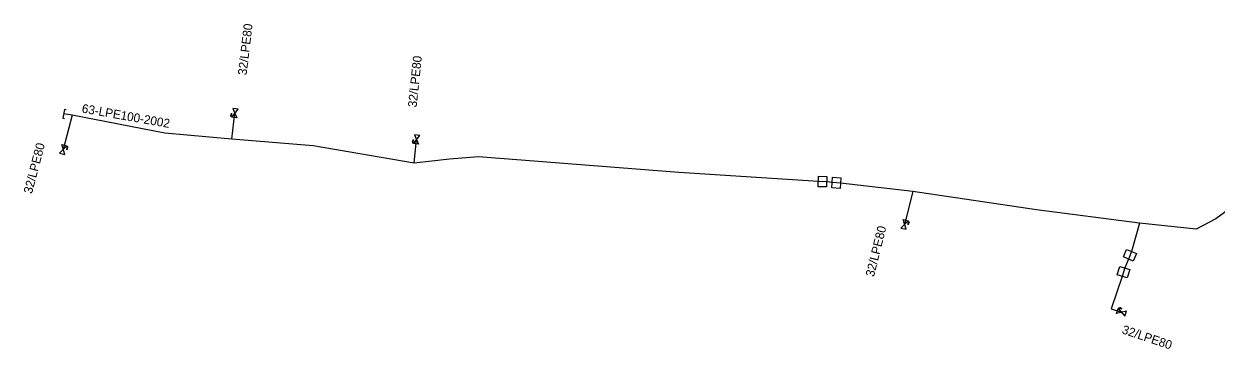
# Model space of a CAD drawing. Extents: x -787723 to -786204, y -1153846 to -1152384.
# Drawn here: x -787461.8 to -787326.5, y -1152544.5 to -1152507.6 of the extents above; entities that cross this region are included whole.
import ezdxf

# ---------------------------------------------------------------- set-up
doc = ezdxf.new("R2010")
doc.units = 0
for name, color, linetype in [('Vrstva 1', 7, 'Continuous'), ('Vrstva 21', 7, 'Continuous'), ('Vrstva 22', 7, 'Continuous'), ('Vrstva 29', 7, 'Continuous'), ('Vrstva 31', 7, 'Continuous'), ('Vrstva 32', 7, 'Continuous')]:
    doc.layers.add(name, color=color, linetype=linetype)

# ---------------------------------------------------------------- blocks, each defined once
blk = doc.blocks.new('DEC063-SN')
at = {"layer": 'Vrstva 1'}
for p, q in [((-0.5, -0.3), (0.5, 0.3)), ((0.5, -0.3), (-0.5, 0.3)), ((-0.5, 0.3), (-0.5, -0.3)), ((0.5, 0.3), (0.5, -0.3)), ((0.126, -0.318), (0.126, -0.458)), ((0.126, -0.384), (0.206, -0.384)), ((0.206, -0.458), (0.206, -0.318)), ((0.366, -0.458), (0.366, -0.318))]:
    blk.add_line(p, q, dxfattribs=at)
for points in [[(0.246, -0.318), (0.246, -0.418), (0.252, -0.438), (0.264, -0.451), (0.281, -0.458), (0.292, -0.458), (0.309, -0.451), (0.321, -0.438), (0.326, -0.418), (0.326, -0.318)], [(0.366, -0.318), (0.418, -0.318), (0.435, -0.325), (0.441, -0.331), (0.446, -0.344), (0.446, -0.364), (0.441, -0.378), (0.435, -0.384), (0.418, -0.391), (0.366, -0.391)]]:
    blk.add_lwpolyline(points, dxfattribs=at)
blk = doc.blocks.new('DEC130')
at = {"layer": 'Vrstva 1'}
blk.add_lwpolyline([(0.2, 0.5), (0, 0.5), (0, -0.5), (0.2, -0.5)], dxfattribs=at)

msp = doc.modelspace()

# ---------------------------------------------------------------- linework, layer by layer
at = {"layer": 'Vrstva 21'}
msp.add_lwpolyline([(-787314.29, -1152521.02), (-787319.27, -1152524.41), (-787326.52, -1152529.72), (-787328.78, -1152530.89), (-787335.19, -1152530.22), (-787346.87, -1152528.71), (-787360.92, -1152526.63), (-787369.11, -1152525.66), (-787370.08, -1152525.59), (-787370.68, -1152525.5), (-787371.63, -1152525.47), (-787387.45, -1152524.45), (-787410.19, -1152522.66), (-787413.47, -1152522.96), (-787417.5, -1152523.41), (-787428.97, -1152521.44), (-787438.18, -1152520.66), (-787445.79, -1152519.98), (-787456.29, -1152517.94), (-787457.28, -1152517.79)], dxfattribs=at)
at = {"layer": 'Vrstva 29'}
for points in [[(-787371.65, -1152526.07), (-787371.61, -1152524.87), (-787370.66, -1152524.9), (-787370.7, -1152526.1)], [(-787370.12, -1152526.19), (-787370.04, -1152524.99), (-787369.07, -1152525.06), (-787369.15, -1152526.26)], [(-787336.65, -1152533.19), (-787335.55, -1152533.65), (-787335.91, -1152534.51), (-787337.01, -1152534.05)], [(-787337.43, -1152535.12), (-787336.29, -1152535.46), (-787336.58, -1152536.43), (-787337.72, -1152536.09)]]:
    msp.add_lwpolyline(points, close=True, dxfattribs=at)
at = {"layer": 'Vrstva 31'}
for points in [[(-787438.18, -1152520.66), (-787437.83, -1152517.73)], [(-787456.29, -1152517.94), (-787457.31, -1152521.84)], [(-787417.5, -1152523.41), (-787417.22, -1152520.72)], [(-787360.92, -1152526.63), (-787361.85, -1152530.35)], [(-787335.19, -1152530.22), (-787336.1, -1152533.42), (-787336.46, -1152534.28), (-787336.86, -1152535.29), (-787337.15, -1152536.26), (-787338.41, -1152539.93), (-787337.22, -1152540.33)]]:
    msp.add_lwpolyline(points, dxfattribs=at)

# ---------------------------------------------------------------- block references
at = {"layer": 'Vrstva 22', "rotation": -10.666019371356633}
msp.add_blockref('DEC130', (-787457.28, -1152517.79), dxfattribs=at)
at = {"layer": 'Vrstva 32'}
for p, rotation in [((-787437.83, -1152517.73), -98.21553887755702), ((-787417.22, -1152520.72), -98.06082224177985), ((-787457.31, -1152521.84), 75.34324998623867), ((-787361.85, -1152530.35), 75.96375828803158), ((-787337.22, -1152540.33), 161.7684999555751)]:
    msp.add_blockref('DEC063-SN', p, dxfattribs=dict(at, rotation=rotation))

# ---------------------------------------------------------------- texts
at = {"layer": 'Vrstva 21'}
msp.add_text('63-LPE100-2002', height=1, rotation=349.951, dxfattribs=at).set_placement((-787455.27, -1152517.64))
at = {"layer": 'Vrstva 31'}
for rotation, p in [(83.188, (-787436.52, -1152513.45)), (84.058, (-787417.22, -1152517.1)), (75.343, (-787460.87, -1152526.93)), (75.964, (-787365.33, -1152536.36)), (341.421, (-787337.27, -1152542.7))]:
    msp.add_text('32/LPE80', height=1, rotation=rotation, dxfattribs=at).set_placement(p)

doc.saveas('drawing.dxf')
